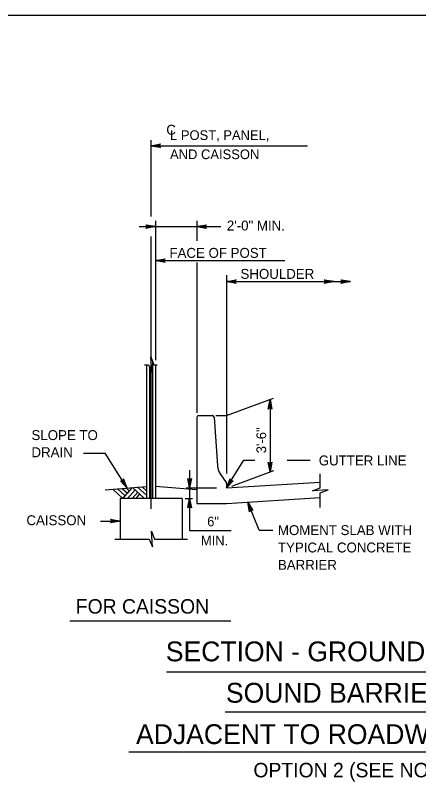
# Model space of a CAD drawing. Extents: x 3761 to 5458, y -616 to 1166.
# Drawn here: x 4942.5 to 5067.4, y 319.4 to 556.7 of the extents above; entities that cross this region are included whole.
import ezdxf

# ---------------------------------------------------------------- set-up
doc = ezdxf.new("R2010")
doc.units = 0
doc.layers.add('1', color=7, linetype='Continuous')
doc.layers.add('2', color=7, linetype='Continuous')

msp = doc.modelspace()

# ---------------------------------------------------------------- linework, layer by layer
at = {"layer": '1'}
for p, q in [((4984.5, 494.44), (4984.5, 518.08)), ((4984.5, 516.32), (5032.9, 516.32)), ((4980.78, 491.27), (5006.16, 491.27)), ((4985.88, 493.12), (4985.88, 449.96)), ((4998.68, 493.12), (4998.68, 486.84)), ((4984.5, 403.88), (4984.5, 488.23)), ((4985.88, 480.75), (5025.93, 480.75)), ((4998.68, 480.18), (4998.68, 433.64)), ((5007.88, 476.23), (5007.88, 414.89)), ((5007.88, 474.25), (5046.21, 474.25)), ((4982.48, 448.53), (4983.74, 448.53)), ((4983.12, 448.53), (4983.12, 407.16)), ((4984.98, 449.47), (4984.98, 407.16)), ((4985.34, 448.53), (4986.39, 448.53)), ((4985.88, 448.53), (4985.88, 407.16)), ((4984.01, 447.87), (4984.01, 407.16)), ((5007.88, 432.76), (5022.45, 438.13)), ((5021.36, 437.73), (5021.36, 415.33)), ((4998.68, 432.23), (4998.68, 405.56)), ((4999.21, 432.76), (5003.52, 432.76)), ((5004.05, 432.27), (5005.11, 417.2)), ((5004.59, 432.76), (5007.88, 432.76)), ((4963.57, 421.13), (4970.34, 421.13)), ((4977.08, 410.32), (4970.34, 421.13)), ((5007.88, 410.36), (5013.23, 418.94)), ((5013.23, 418.94), (5016.59, 418.94)), ((5026.65, 418.94), (5033.81, 418.94)), ((4996.44, 415.84), (4996.44, 397.2)), ((5009.47, 410.95), (5022.49, 415.74)), ((5006.09, 414.47), (5007.78, 412.1)), ((5036.91, 410.45), (5036.91, 414.79)), ((4970.32, 409.76), (4983.12, 410.82)), ((4975.8, 407.14), (4978.79, 410.5)), ((4982.53, 407.16), (4978.79, 410.5)), ((4983.07, 408.1), (4980.28, 410.58)), ((4983.07, 409.52), (4981.78, 410.67)), ((4998.49, 409.77), (4985.88, 410.82)), ((5007.88, 410.36), (5036.91, 412.2)), ((5007.88, 411.79), (5007.88, 410.36)), ((4972.63, 409.97), (4975.77, 407.16)), ((4974.12, 410.05), (4976.5, 407.93)), ((4975.62, 410.14), (4977.21, 408.72)), ((4976.79, 410.3), (4977.82, 409.38)), ((4977.24, 407.16), (4979.58, 409.79)), ((4978.66, 407.16), (4980.37, 409.09)), ((4979.86, 407.16), (4981.05, 408.51)), ((4995.35, 410.36), (5004.79, 410.36)), ((5002.43, 410.36), (5004.48, 410.36)), ((5036.91, 404.33), (5036.91, 408.85)), ((4974.9, 407.16), (4974.9, 394.57)), ((4994.1, 407.16), (4974.9, 407.16)), ((4994.1, 407.16), (4994.1, 394.57)), ((4995.05, 407.16), (4997.32, 407.16)), ((5007.88, 405.56), (5036.91, 407.4)), ((5017.96, 397.28), (5014.51, 405.98)), ((4998.68, 405.56), (5007.88, 405.56)), ((4968.9, 400.11), (4974.9, 400.11)), ((4996.44, 397.2), (5009.35, 397.2)), ((5017.96, 397.28), (5022.22, 397.28)), ((4973.34, 394.57), (4983.96, 394.57)), ((4985.56, 394.57), (4995.79, 394.57)), ((4959.39, 369.28), (5009.19, 369.28)), ((4989.29, 353.42), (5135.11, 353.42)), ((5007.44, 341.04), (5115.69, 341.04)), ((4977.63, 328.65), (5145.41, 328.65))]:
    msp.add_line(p, q, dxfattribs=at)
for points in [[(4984.5, 516.32), (4987.48, 516.88), (4987.25, 516.72), (4987.13, 516.52), (4987.1, 516.32), (4987.13, 516.12), (4987.25, 515.92), (4987.48, 515.76), (4984.5, 516.32), (4987.25, 515.92), (4987.13, 516.12), (4984.5, 516.32), (4987.1, 516.32), (4987.13, 516.52), (4984.5, 516.32), (4987.25, 516.72)], [(4985.88, 491.27), (4982.9, 490.71), (4983.01, 490.79), (4983.13, 490.87), (4983.19, 490.97), (4983.25, 491.07), (4983.26, 491.17), (4983.28, 491.27), (4983.26, 491.37), (4983.25, 491.47), (4983.19, 491.57), (4983.13, 491.67), (4983.01, 491.75), (4982.9, 491.83), (4985.88, 491.27), (4983.01, 491.75), (4983.13, 491.67), (4985.88, 491.27), (4983.19, 491.57), (4983.25, 491.47), (4985.88, 491.27), (4983.26, 491.37), (4983.28, 491.27), (4985.88, 491.27), (4983.26, 491.17), (4983.25, 491.07), (4985.88, 491.27), (4983.19, 490.97), (4983.13, 490.87), (4985.88, 491.27), (4983.01, 490.79)], [(4998.68, 491.27), (5001.66, 491.83), (5001.55, 491.75), (5001.43, 491.67), (5001.37, 491.57), (5001.31, 491.47), (5001.3, 491.37), (5001.28, 491.27), (5001.3, 491.17), (5001.31, 491.07), (5001.37, 490.97), (5001.43, 490.87), (5001.55, 490.79), (5001.66, 490.71), (4998.68, 491.27), (5001.55, 490.79), (5001.43, 490.87), (4998.68, 491.27), (5001.37, 490.97), (5001.31, 491.07), (4998.68, 491.27), (5001.3, 491.17), (5001.28, 491.27), (4998.68, 491.27), (5001.3, 491.37), (5001.31, 491.47), (4998.68, 491.27), (5001.37, 491.57), (5001.43, 491.67), (4998.68, 491.27), (5001.55, 491.75)], [(4985.88, 480.75), (4988.86, 481.31), (4988.63, 481.15), (4988.51, 480.95), (4988.48, 480.75), (4988.51, 480.55), (4988.63, 480.35), (4988.86, 480.19), (4985.88, 480.75), (4988.63, 480.35), (4988.51, 480.55), (4985.88, 480.75), (4988.48, 480.75), (4988.51, 480.95), (4985.88, 480.75), (4988.63, 481.15)], [(5007.88, 474.25), (5010.86, 474.81), (5010.63, 474.65), (5010.51, 474.45), (5010.48, 474.25), (5010.51, 474.05), (5010.63, 473.85), (5010.86, 473.69), (5007.88, 474.25), (5010.63, 473.85), (5010.51, 474.05), (5007.88, 474.25), (5010.48, 474.25), (5010.51, 474.45), (5007.88, 474.25), (5010.63, 474.65)], [(5041.09, 474.25), (5038.11, 473.69), (5038.22, 473.77), (5038.34, 473.85), (5038.4, 473.95), (5038.45, 474.05), (5038.47, 474.15), (5038.49, 474.25), (5038.47, 474.35), (5038.45, 474.45), (5038.4, 474.55), (5038.34, 474.65), (5038.22, 474.73), (5038.11, 474.81), (5041.09, 474.25), (5038.22, 474.73), (5038.34, 474.65), (5041.09, 474.25), (5038.4, 474.55), (5038.45, 474.45), (5041.09, 474.25), (5038.47, 474.35), (5038.49, 474.25), (5041.09, 474.25), (5038.47, 474.15), (5038.45, 474.05), (5041.09, 474.25), (5038.4, 473.95), (5038.34, 473.85), (5041.09, 474.25), (5038.22, 473.77)], [(5046.21, 474.25), (5043.23, 473.69), (5043.34, 473.77), (5043.46, 473.85), (5043.52, 473.95), (5043.57, 474.05), (5043.59, 474.15), (5043.61, 474.25), (5043.59, 474.35), (5043.57, 474.45), (5043.52, 474.55), (5043.46, 474.65), (5043.34, 474.73), (5043.23, 474.81), (5046.21, 474.25), (5043.34, 474.73), (5043.46, 474.65), (5046.21, 474.25), (5043.52, 474.55), (5043.57, 474.45), (5046.21, 474.25), (5043.59, 474.35), (5043.61, 474.25), (5046.21, 474.25), (5043.59, 474.15), (5043.57, 474.05), (5046.21, 474.25), (5043.52, 473.95), (5043.46, 473.85), (5046.21, 474.25), (5043.34, 473.77)], [(4983.74, 448.53), (4984.72, 446.13), (4984.42, 450.93), (4985.34, 448.53)], [(5021.36, 437.73), (5021.92, 434.75), (5021.84, 434.86), (5021.76, 434.98), (5021.66, 435.04), (5021.56, 435.09), (5021.46, 435.11), (5021.36, 435.13), (5021.26, 435.11), (5021.16, 435.09), (5021.06, 435.04), (5020.96, 434.98), (5020.88, 434.86), (5020.8, 434.75), (5021.36, 437.73), (5020.88, 434.86), (5020.96, 434.98), (5021.36, 437.73), (5021.06, 435.04), (5021.16, 435.09), (5021.36, 437.73), (5021.26, 435.11), (5021.36, 435.13), (5021.36, 437.73), (5021.46, 435.11), (5021.56, 435.09), (5021.36, 437.73), (5021.66, 435.04), (5021.76, 434.98), (5021.36, 437.73), (5021.84, 434.86)], [(5021.36, 415.33), (5020.8, 418.31), (5020.88, 418.2), (5020.96, 418.08), (5021.06, 418.02), (5021.16, 417.96), (5021.26, 417.95), (5021.36, 417.93), (5021.46, 417.95), (5021.56, 417.96), (5021.66, 418.02), (5021.76, 418.08), (5021.84, 418.2), (5021.92, 418.31), (5021.36, 415.33), (5021.84, 418.2), (5021.76, 418.08), (5021.36, 415.33), (5021.66, 418.02), (5021.56, 417.96), (5021.36, 415.33), (5021.46, 417.95), (5021.36, 417.93), (5021.36, 415.33), (5021.26, 417.95), (5021.16, 417.96), (5021.36, 415.33), (5021.06, 418.02), (5020.96, 418.08), (5021.36, 415.33), (5020.88, 418.2)], [(4977.08, 410.32), (4975.99, 413.15), (4975.98, 413.01), (4975.97, 412.87), (4975.92, 412.77), (4975.87, 412.67), (4975.79, 412.6), (4975.71, 412.53), (4975.62, 412.49), (4975.53, 412.46), (4975.41, 412.45), (4975.29, 412.45), (4975.17, 412.51), (4975.04, 412.56), (4977.08, 410.32), (4975.17, 412.51), (4975.29, 412.45), (4977.08, 410.32), (4975.41, 412.45), (4975.53, 412.46), (4977.08, 410.32), (4975.62, 412.49), (4975.71, 412.53), (4977.08, 410.32), (4975.79, 412.6), (4975.87, 412.67), (4977.08, 410.32), (4975.92, 412.77), (4975.97, 412.87), (4977.08, 410.32), (4975.98, 413.01)], [(4996.44, 410.36), (4995.88, 413.35), (4995.96, 413.23), (4996.04, 413.12), (4996.14, 413.06), (4996.24, 413), (4996.34, 412.98), (4996.44, 412.96), (4996.54, 412.98), (4996.64, 413), (4996.74, 413.06), (4996.84, 413.12), (4996.92, 413.23), (4997, 413.35), (4996.44, 410.36), (4996.92, 413.23), (4996.84, 413.12), (4996.44, 410.36), (4996.74, 413.06), (4996.64, 413), (4996.44, 410.36), (4996.54, 412.98), (4996.44, 412.96), (4996.44, 410.36), (4996.34, 412.98), (4996.24, 413), (4996.44, 410.36), (4996.14, 413.06), (4996.04, 413.12), (4996.44, 410.36), (4995.96, 413.23)], [(5007.88, 410.36), (5008.97, 413.2), (5008.98, 413.06), (5008.99, 412.92), (5009.04, 412.81), (5009.09, 412.71), (5009.17, 412.64), (5009.25, 412.58), (5009.34, 412.54), (5009.44, 412.5), (5009.55, 412.5), (5009.67, 412.5), (5009.8, 412.55), (5009.92, 412.61), (5007.88, 410.36), (5009.8, 412.55), (5009.67, 412.5), (5007.88, 410.36), (5009.55, 412.5), (5009.44, 412.5), (5007.88, 410.36), (5009.34, 412.54), (5009.25, 412.58), (5007.88, 410.36), (5009.17, 412.64), (5009.09, 412.71), (5007.88, 410.36), (5009.04, 412.81), (5008.99, 412.92), (5007.88, 410.36), (5008.98, 413.06)], [(5036.91, 408.85), (5039.31, 409.82), (5034.51, 409.53), (5036.91, 410.45)], [(4996.44, 407.16), (4997, 404.18), (4996.92, 404.3), (4996.84, 404.41), (4996.74, 404.47), (4996.64, 404.53), (4996.54, 404.55), (4996.44, 404.56), (4996.34, 404.55), (4996.24, 404.53), (4996.14, 404.47), (4996.04, 404.41), (4995.96, 404.3), (4995.88, 404.18), (4996.44, 407.16), (4995.96, 404.3), (4996.04, 404.41), (4996.44, 407.16), (4996.14, 404.47), (4996.24, 404.53), (4996.44, 407.16), (4996.34, 404.55), (4996.44, 404.56), (4996.44, 407.16), (4996.54, 404.55), (4996.64, 404.53), (4996.44, 407.16), (4996.74, 404.47), (4996.84, 404.41), (4996.44, 407.16), (4996.92, 404.3)], [(5014.51, 405.98), (5016.06, 403.38), (5015.95, 403.46), (5015.83, 403.54), (5015.72, 403.56), (5015.6, 403.58), (5015.5, 403.56), (5015.4, 403.54), (5015.32, 403.49), (5015.23, 403.44), (5015.15, 403.35), (5015.08, 403.26), (5015.05, 403.13), (5015.01, 402.99), (5014.51, 405.98), (5015.05, 403.13), (5015.08, 403.26), (5014.51, 405.98), (5015.15, 403.35), (5015.23, 403.44), (5014.51, 405.98), (5015.32, 403.49), (5015.4, 403.54), (5014.51, 405.98), (5015.5, 403.56), (5015.6, 403.58), (5014.51, 405.98), (5015.72, 403.56), (5015.83, 403.54), (5014.51, 405.98), (5015.95, 403.46)], [(4974.9, 400.11), (4971.91, 399.6), (4972.14, 399.75), (4972.26, 399.95), (4972.3, 400.15), (4972.27, 400.35), (4972.15, 400.55), (4971.92, 400.71), (4974.9, 400.11), (4972.15, 400.55), (4972.27, 400.35), (4974.9, 400.11), (4972.3, 400.15), (4972.26, 399.95), (4974.9, 400.11), (4972.14, 399.75)], [(4983.96, 394.57), (4984.93, 392.17), (4984.64, 396.97), (4985.56, 394.57)]]:
    msp.add_lwpolyline(points, dxfattribs=at)
for centre, radius, start, end in [((4999.21, 432.23), 0.533, 90, 180), ((5003.52, 432.23), 0.533, 4.0219, 90), ((5010.43, 417.57), 5.33, 184.0219, 215.5414), ((5007.35, 411.79), 0.533, 0, 35.5414)]:
    msp.add_arc(centre, radius, start, end, dxfattribs=at)
at = {"layer": '2'}
msp.add_line((4642.34, 556.69), (5428.34, 556.69), dxfattribs=at)

# ---------------------------------------------------------------- texts
at = {"layer": '1'}
for s, height, p in [('C', 3.07, (4989.24, 519.74)), ('L POST, PANEL,', 3, (4990.39, 518.1)), ('AND CAISSON', 3, (4990.39, 512.17)), ('2\'-0" MIN.', 3.072, (5007.96, 490.07)), ('FACE OF POST', 3.0721, (4990.21, 481.61)), ('SHOULDER', 3.072, (5012.21, 475.11)), ('SLOPE TO', 3.072, (4947.49, 425.2)), ('DRAIN', 3.072, (4947.49, 419.89)), ('GUTTER LINE', 3.0721, (5036.44, 417.35)), ('CAISSON', 3.072, (4945.93, 398.85)), ('6"', 3, (5001.89, 398.49)), ('MOMENT SLAB WITH', 3.0721, (5023.79, 395.78)), ('MIN.', 3, (4999.93, 392.56)), ('TYPICAL CONCRETE', 3.0721, (5023.79, 390.4)), ('BARRIER', 3.072, (5023.79, 385.03)), ('FOR CAISSON', 4.48, (4961.2, 371.47)), ('SECTION - GROUND MOUNTED', 6.1439, (4989.08, 356.7)), ('SOUND BARRIER WALL', 6.1439, (5007.68, 343.89)), ('ADJACENT TO ROADWAY BARRIER', 6.1439, (4979.86, 331.08)), ('OPTION 2 (SEE NOTE 2)', 4.48, (5016.2, 320.79))]:
    msp.add_text(s, height=height, dxfattribs=at).set_placement(p)
msp.add_text('3\'-6"', height=3, rotation=90, dxfattribs=at).set_placement((5020.14, 421.12))

doc.saveas('drawing.dxf')
